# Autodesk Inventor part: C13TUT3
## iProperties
Created: 2005-03
Part Number: C13TUT3
Document SubType Name: Modeling
Designer: CADCIM
Manufacturer: Standard
Standards Organization: Custom
Density: 1 g/cm^3
Author: CADCIM
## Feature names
1. Sweep1
